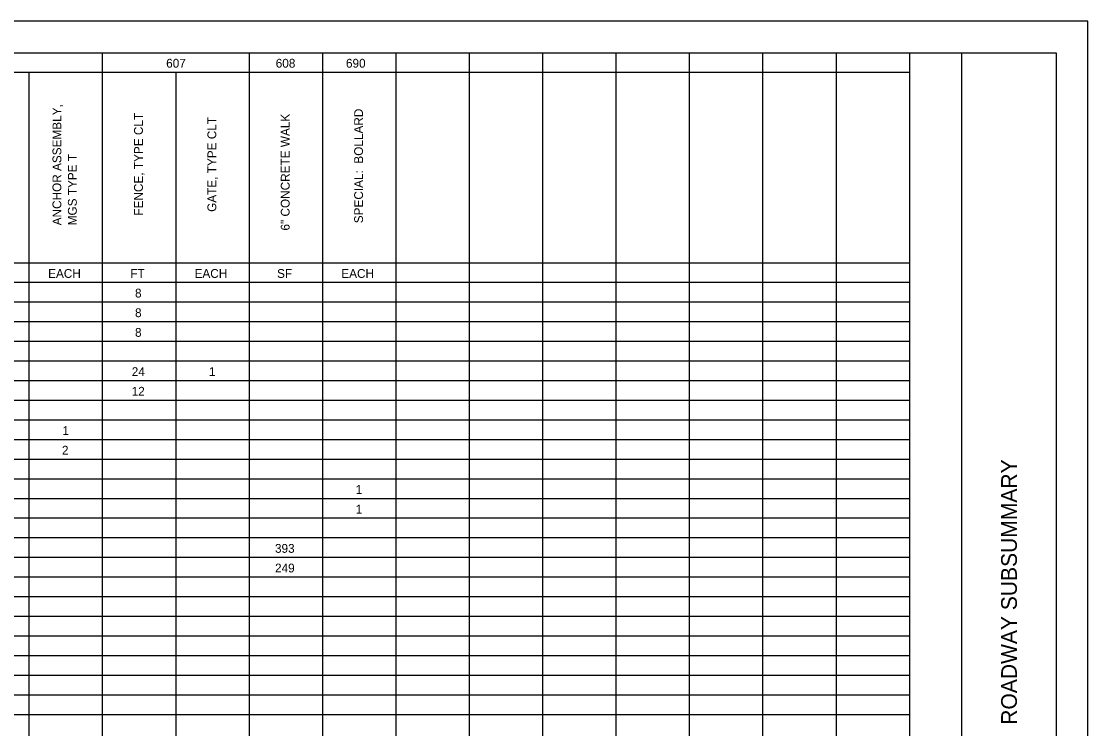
# Model space of a CAD drawing. Extents: x 0 to 34, y 0 to 22.
# Drawn here: x 17.05 to 34, y 10.76 to 22 of the extents above; entities that cross this region are included whole.
import ezdxf

# ---------------------------------------------------------------- set-up
doc = ezdxf.new("R2010")
doc.units = 0
for name, color, linetype in [('Default', 7, 'Continuous'), ('SH_Border', 7, 'Continuous'), ('SH_Cut_Line', 7, 'Continuous'), ('SH_Data', 7, 'Continuous')]:
    doc.layers.add(name, color=color, linetype=linetype)

msp = doc.modelspace()

# ---------------------------------------------------------------- linework, layer by layer
at = {"layer": 'Default'}
for p, q in [((31.167, 18.16), (7.843, 18.16)), ((31.167, 17.536), (1.5, 17.536)), ((31.167, 17.224), (1.5, 17.224)), ((31.167, 16.912), (1.5, 16.912)), ((31.167, 16.6), (1.5, 16.6)), ((31.167, 16.288), (1.5, 16.288)), ((31.167, 15.976), (1.5, 15.976)), ((31.167, 15.664), (1.5, 15.664)), ((31.167, 15.352), (1.5, 15.352)), ((31.167, 15.04), (1.5, 15.04)), ((31.167, 14.728), (1.5, 14.728)), ((31.167, 14.416), (1.5, 14.416)), ((31.167, 14.104), (1.5, 14.104)), ((31.167, 13.792), (1.5, 13.792)), ((31.167, 13.48), (1.5, 13.48)), ((31.167, 13.168), (1.5, 13.168)), ((31.167, 12.856), (1.5, 12.856)), ((31.167, 12.544), (1.5, 12.544)), ((31.167, 12.232), (1.5, 12.232)), ((31.167, 11.92), (1.5, 11.92)), ((31.167, 11.608), (1.5, 11.608)), ((31.167, 11.296), (1.5, 11.296)), ((31.167, 10.984), (1.5, 10.984))]:
    msp.add_line(p, q, dxfattribs=at)
at = {"layer": 'SH_Border'}
msp.add_line((32, 0.5), (32, 21.5), dxfattribs=at)
msp.add_lwpolyline([(1.5, 21.5), (33.5, 21.5), (33.5, 0.5), (1.5, 0.5)], close=True, dxfattribs=at)
at = {"layer": 'SH_Cut_Line'}
msp.add_lwpolyline([(0, 0), (34, 0), (34, 22), (0, 22)], close=True, dxfattribs=at)
at = {"layer": 'SH_Data'}
for p, q in [((18.341, 21.498), (18.341, 0.686)), ((20.673, 21.5), (20.673, 0.688)), ((21.839, 21.5), (21.839, 0.688)), ((21.839, 21.5), (21.839, 0.688)), ((21.839, 21.5), (21.839, 0.688)), ((21.839, 21.498), (21.839, 0.686)), ((23.005, 21.5), (23.005, 0.688)), ((24.171, 21.5), (24.171, 0.688)), ((25.337, 21.5), (25.337, 0.688)), ((26.503, 21.5), (26.503, 0.688)), ((27.669, 21.5), (27.669, 0.688)), ((28.835, 21.5), (28.835, 0.688)), ((30.001, 21.5), (30.001, 0.688)), ((31.167, 21.5), (31.167, 0.688)), ((31.167, 21.5), (31.167, 0.688)), ((31.167, 21.188), (7.843, 21.188)), ((17.175, 21.188), (17.175, 0.688)), ((18.341, 21.188), (18.341, 0.688)), ((18.341, 21.188), (18.341, 0.688)), ((18.341, 21.188), (18.341, 0.688)), ((19.507, 21.188), (19.507, 0.688)), ((20.673, 21.188), (20.673, 0.688)), ((31.167, 17.848), (1.5, 17.848))]:
    msp.add_line(p, q, dxfattribs=at)

# ---------------------------------------------------------------- texts
for s, p in [('607', (19.356, 21.264)), ('608', (21.097, 21.264)), ('690', (22.213, 21.264)), ('EACH', (17.48, 17.924)), ('FT', (18.787, 17.924)), ('EACH', (19.807, 17.924)), ('SF', (21.118, 17.924)), ('EACH', (22.139, 17.924)), ('8', (18.861, 17.612)), ('8', (18.861, 17.3)), ('8', (18.861, 16.988)), ('24', (18.809, 16.364)), ('1', (20.035, 16.364)), ('12', (18.807, 16.052)), ('1', (17.708, 15.428)), ('2', (17.7, 15.116)), ('1', (22.367, 14.492)), ('1', (22.367, 14.18)), ('393', (21.085, 13.556)), ('249', (21.086, 13.244))]:
    msp.add_text(s, height=0.14, dxfattribs=at).set_placement(p)
for s, height, p in [('ANCHOR ASSEMBLY, ', 0.14, (17.69, 18.759)), ('FENCE, TYPE CLT', 0.14, (18.986, 18.913)), ('6" CONCRETE WALK', 0.14, (21.318, 18.676)), ('SPECIAL:  BOLLARD', 0.14, (22.484, 18.792)), ('GATE, TYPE CLT', 0.14, (20.152, 18.973)), ('MGS TYPE T', 0.14, (17.935, 18.759)), ('ROADWAY SUBSUMMARY', 0.25, (32.875, 10.824))]:
    msp.add_text(s, height=height, rotation=90, dxfattribs=at).set_placement(p)

doc.saveas('drawing.dxf')
